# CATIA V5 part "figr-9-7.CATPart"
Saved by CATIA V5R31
Part number: Part2
Bounding box of the stored display mesh (mm): x -96.278 to 96.278, y -96.278 to 96.278, z -26.878 to 0
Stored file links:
  D:\PROJECTS\Project 2021\US EDITION\CATIA V5 6R 2021\Resources\Part Files\c09_catia_v5_6r2021_prt\c09_catia_v5_6r2021_prt\figr-9-7.CATPart
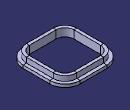
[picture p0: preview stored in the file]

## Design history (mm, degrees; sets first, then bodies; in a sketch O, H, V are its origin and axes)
Body1 (main body)
  Sketch1 on xy-plane, origin (0, 0, 0), H (1, 0, 0), V (0, 1, 0)
    point P1 (-75, 75)
    line L1 (-45, 75) -> (45, 75)
    line L2 (75, 45) -> (75, -45)
    line L3 (45, -75) -> (-45, -75)
    line L4 (-75, -45) -> (-75, 45)
    point P2 (75, 75)
    point P3 (75, -75)
    point P4 (-75, -75)
    axis line L5 (75, -75) -> (-75, 75)
    arc A1 centre (45, -45) radius 30 from (75, -45) to (45, -75) cw
    arc A2 centre (45, 45) radius 30 from (45, 75) to (75, 45) cw
    arc A3 centre (-45, 45) radius 30 from (-45, 75) to (-75, 45) ccw
    arc A4 centre (-45, -45) radius 30 from (-45, -75) to (-75, -45) cw
    distance P2 P3 = 150
    distance P3 P4 = 150
    radius A1 = 30
    radius A2 = 30
    radius A3 = 30
    radius A4 = 30
    horizontal: L1 H, L3 H
    vertical: L2 V, L4 V
    midpoint: O L5
    coincidence: L2 P3, L3 P3, L1 P2, L2 P2, L1 P1, L4 P1, L3 P4, L4 P4
    tangency: A1 L2, A1 L3, A2 L1, A2 L2, A3 L1, A3 L4, A4 L3, A4 L4
  Sketch2 on yz-plane, origin (0, 0, 0), H (0, 1, 0), V (0, 0, 1)
    point P1 (85, 0)
    line L1 (85, 0) -> (85, -16.8782)
    line L2 (85, -16.8782) -> (96.2781, -16.8782)
    line L3 (96.2781, -16.8782) -> (96.2781, -26.8782)
    line L4 (96.2781, -26.8782) -> (75, -26.8782)
    line L5 (75, -26.8782) -> (75, 0)
    point P6 (75, 0)
    line L6 (75, 0) -> (85, 0)
    reference projected point E1 (75, 0) from edge of Sketch1
    length L3 = 10
    length L6 = 10
    coincidence: P1 H, P6 H, P6 E1
    vertical: L1 V, L3 V, L5 V
    horizontal: L2 H, L4 H, L6 H
  Rib1: profile Sketch2, centre curve Sketch1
